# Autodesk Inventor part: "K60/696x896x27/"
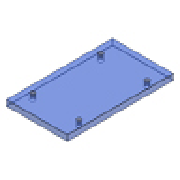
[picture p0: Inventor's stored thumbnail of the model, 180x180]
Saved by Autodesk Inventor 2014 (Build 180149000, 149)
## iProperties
IsCustomPart: 1
Created: 2009-11
Part Number: "K60/696x896x27/"
Material: DIN 1.1730
Description: Ejector Retainer Plate
Document SubType Name: Modeling
Designer: gaom
Standard Revision: 1
Manufacturer: HASCO
Language: en-US
Size Designation: "696x896x27/"
Categories: <MemberInstance><Categories><Category DisplayName="Mold" InternalName="349578f2-f4d4-4954-8c09-8e99297a61c0" Mnemonic="MOLD"><Category DisplayName="Mold Plates"
Density: 7.82 g/cm^3
Appearance: Clear - Blue
Author: gaom
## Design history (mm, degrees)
sketch "Sketch1"
  geometry: L1 (-262, 448)-(262, 448); L2 (262, 448)-(262, -448); L3 (262, -448)-(-262, -448); L4 (-262, -448)-(-262, 448); 4 further points
  constraints: 8 end point, 2 midpoint, 2 parallel, 1 horizontal, 1 horizontal alignment, 1 perpendicular, 1 vertical alignment
  dimensions: "d84" = 524 distance between parallel lines of L2 L4 (= W_); "d85" = 896 distance between parallel lines of L3 L1 (= L); "d88" = 244 horizontal distance of point (0, 0) point (-244, 405) (= 0.5 x S2_W); "d89" = 405 vertical distance of point (0, 0) point (-244, 405) (= 0.5 x S2_L)
extrude "Extrusion1" new body sketch "Sketch1" distance "d20" = 27 (= H_); taper "d30" = 0 deg
sketch "Sketch2"
  geometry: 4 further points
hole "Hole8" sketch "Sketch2" at (-142, -279.032), (78, -279.032), (-78, 279.032), (142, 279.032) diameter "d119" = 3.6; stored, may be unused: countersink angle "d123" = 90 deg, drill point angle "d125" = 0 deg; dims "d120" = 6, "d121" = 7, "d122" = 3, "d124" = 8
sketch "Sketch3"
  geometry: 4 further points
hole "Hole9" sketch "Sketch3" at (-154, -180.032), (66, -180.032), (-66, 180.032), (154, 180.032) diameter "d126" = 3.6; stored, may be unused: countersink angle "d130" = 90 deg, drill point angle "d132" = 0 deg; dims "d127" = 6, "d128" = 7, "d129" = 3, "d131" = 8
sketch "Sketch4"
  geometry: 4 further points
hole "Hole10" sketch "Sketch4" at (-78, -279.032), (142, -279.032), (-142, 279.032), (78, 279.032) diameter "d133" = 3.6; stored, may be unused: countersink angle "d137" = 90 deg, drill point angle "d139" = 0 deg; dims "d134" = 6, "d135" = 7, "d136" = 3, "d138" = 8
sketch "Sketch5"
  geometry: 4 further points
hole "Hole11" sketch "Sketch5" at (-66, -180.032), (154, -180.032), (-154, 180.032), (66, 180.032) diameter "d140" = 3.6; stored, may be unused: countersink angle "d144" = 90 deg, drill point angle "d146" = 0 deg; dims "d141" = 6, "d142" = 7, "d143" = 3, "d145" = 8
sketch "Sketch6"
  geometry: 4 further points
hole "Hole12" sketch "Sketch6" at (-154, -65.032), (66, -65.032), (-66, 65.032), (154, 65.032) diameter "d147" = 3.6; stored, may be unused: countersink angle "d151" = 90 deg, drill point angle "d153" = 0 deg; dims "d148" = 6, "d149" = 7, "d150" = 3, "d152" = 8
sketch "Sketch7"
  geometry: 4 further points
hole "Hole13" sketch "Sketch7" at (-66, -65.032), (154, -65.032), (-154, 65.032), (66, 65.032) diameter "d154" = 3.6; stored, may be unused: countersink angle "d158" = 90 deg, drill point angle "d160" = 0 deg; dims "d155" = 6, "d156" = 7, "d157" = 3, "d159" = 8
feature "Sculpt25"
feature "Sculpt26"
feature "Sculpt27"
feature "Sculpt28"
feature "Sculpt29"
feature "Sculpt30"
feature "Sculpt31"
feature "Sculpt32"
body "Solid1"
hole "Hole1" sketch "Sketch1" diameter "d90" = 10.106; stored, may be unused: countersink angle "d94" = 90 deg, drill point angle "d96" = 0 deg; dims "d91" = 6, "d92" = 4, "d93" = 2, "d95" = 27 (= H_)
pattern_linear "Rectangular Pattern1" dims "d106" = 810 (computed from S2_L, Nl), "d109" = 488 (computed from S2_W, Nw)
chamfer "Chamfer1" distance "d116" = 0.5; stored, may be unused: second distance "d117" = 2, angle "d118" = 45 deg
feature "Surface25"
body "Srf25"
feature "Surface26"
body "Srf26"
feature "Surface27"
body "Srf27"
feature "Surface28"
body "Srf28"
feature "Surface29"
body "Srf29"
feature "Surface30"
body "Srf30"
feature "Surface31"
body "Srf31"
feature "Surface32"
body "Srf32"
other parameters: "L" = 896 [user parameter; used in 1 equation term], "W_" = 524 [user parameter; used in 1 equation term], "H_" = 27 [user parameter; used in 2 equation terms], "S2_W" = 488 [user parameter; used in 2 equation terms]
